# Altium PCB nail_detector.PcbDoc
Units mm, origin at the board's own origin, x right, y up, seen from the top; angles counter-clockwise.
Board outline 180 x 100 mm, 2 copper layers (Top Layer, Bottom Layer); 116 components, 102 nets, 420 pads, 177 vias.
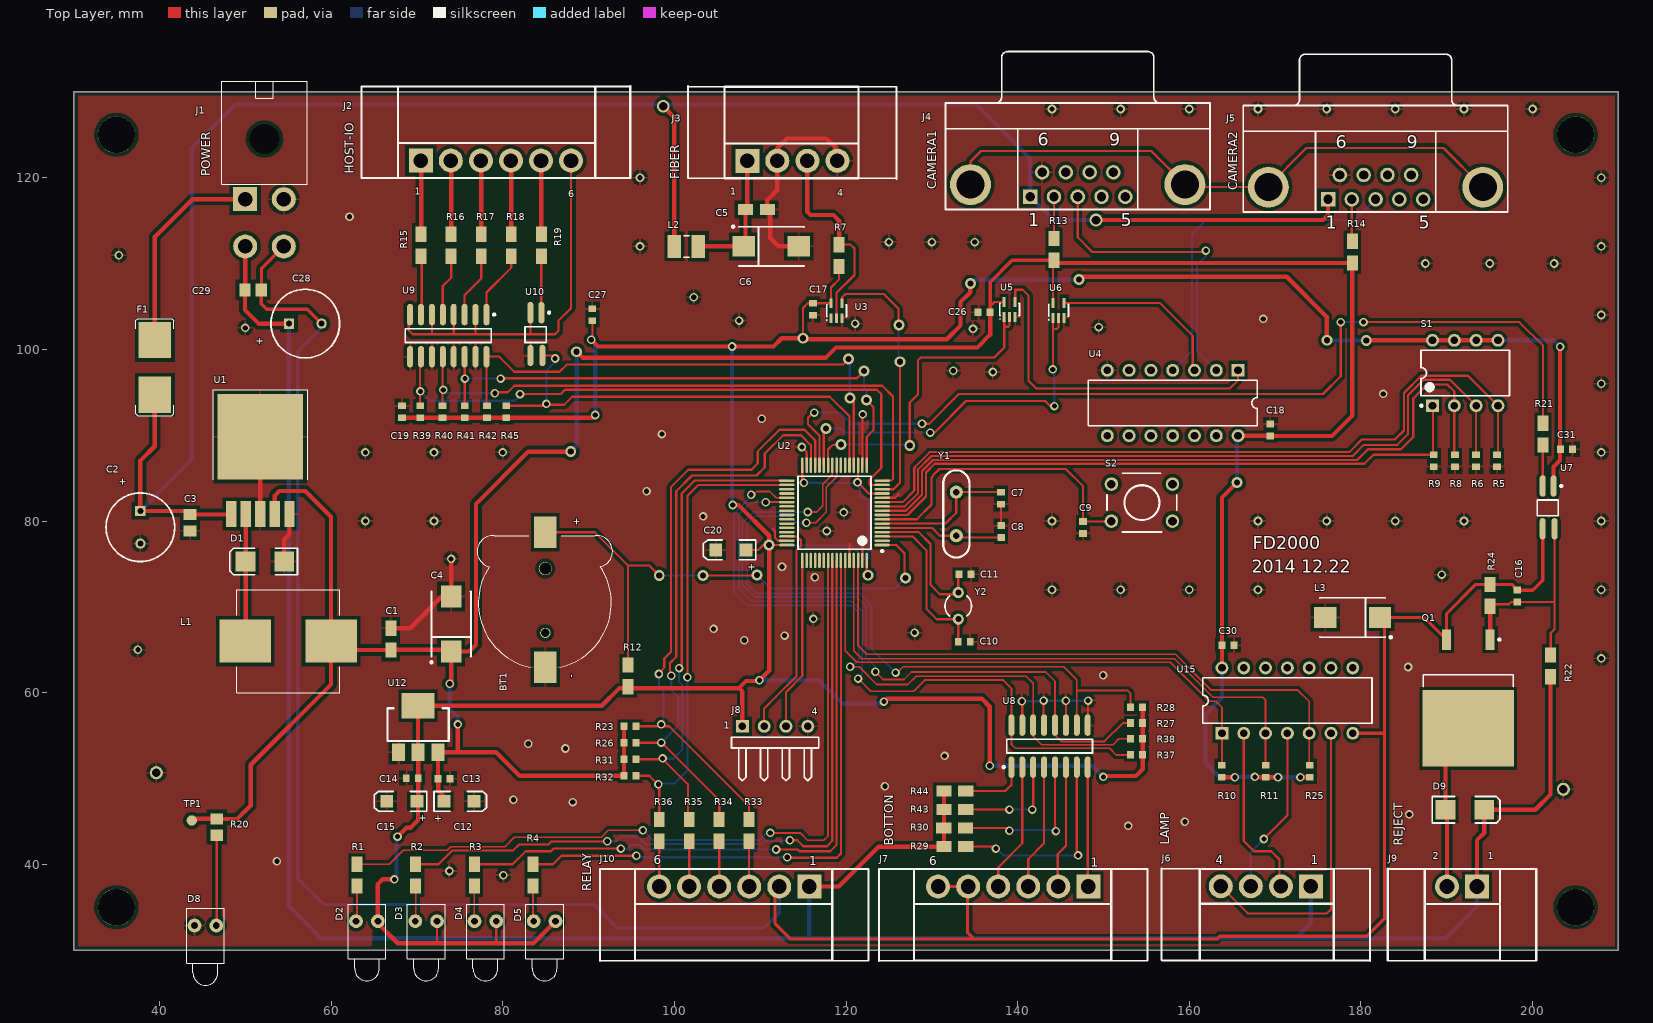
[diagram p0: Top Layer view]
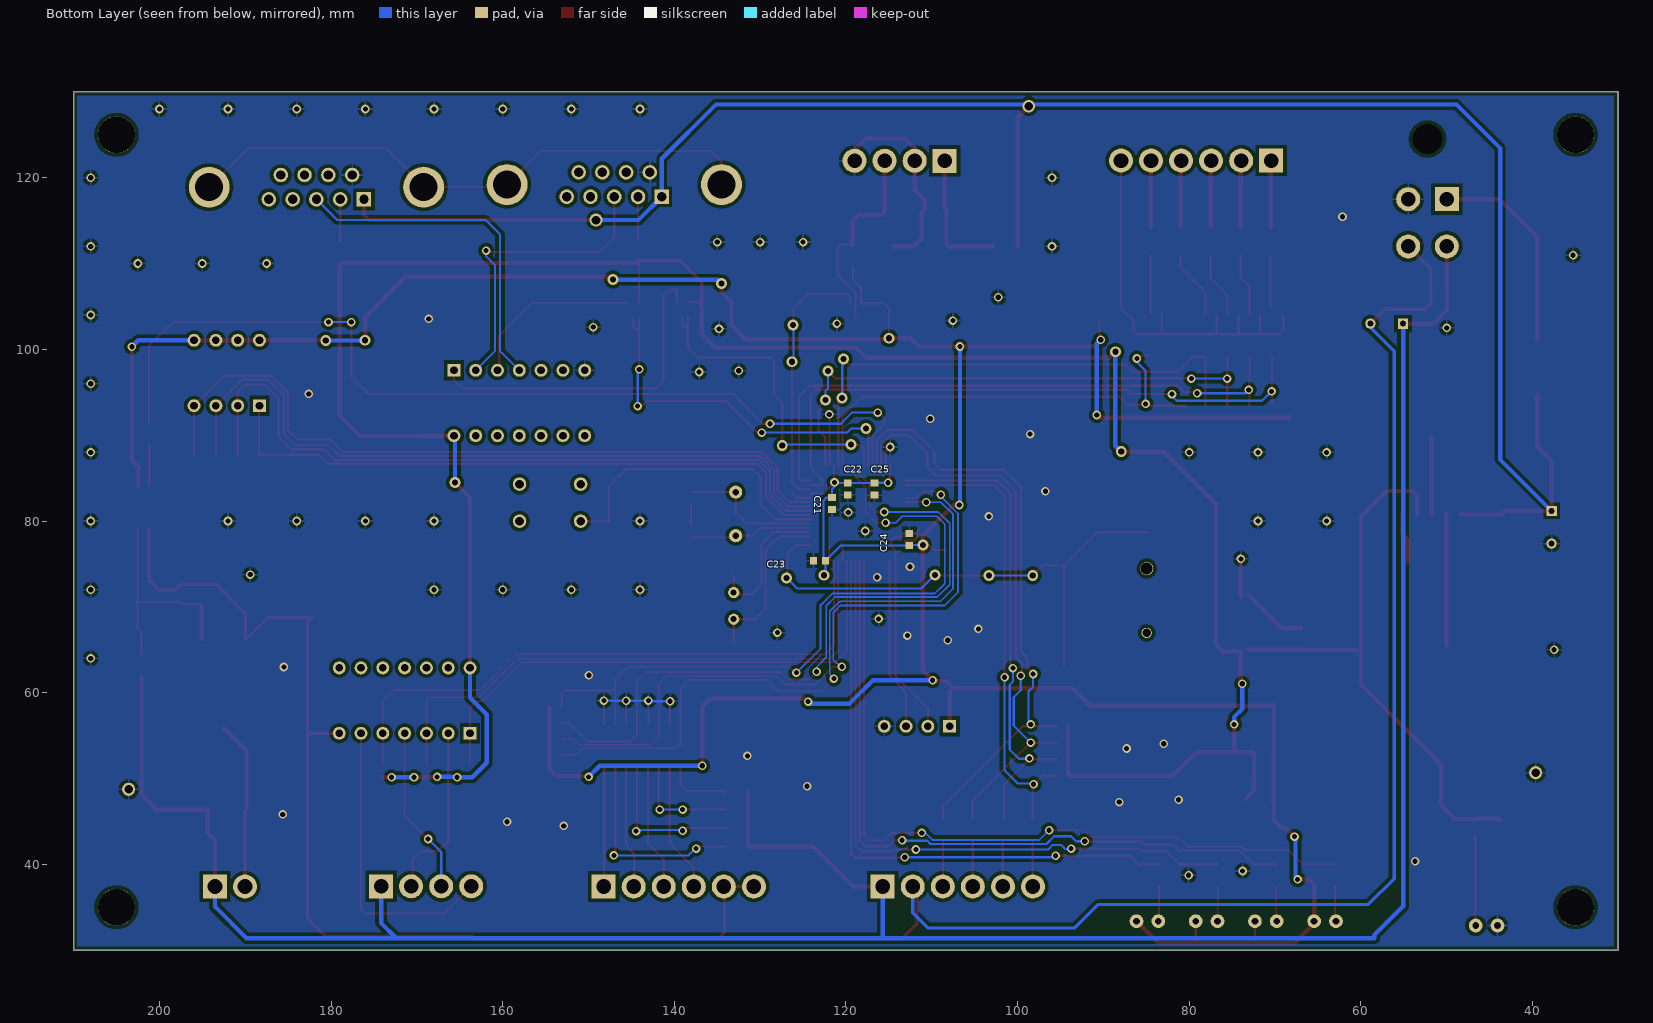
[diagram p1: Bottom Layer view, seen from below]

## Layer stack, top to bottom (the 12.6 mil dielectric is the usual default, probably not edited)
Top Layer: signal copper 0.0356
Dielectric: dielectric 0.32, FR-4, Dk 4.8
Bottom Layer: signal copper 0.0356

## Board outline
30,130 210,130 210,30 30,30

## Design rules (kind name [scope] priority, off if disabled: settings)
Clearance Clearance_u2 [InComponent('U2')] p1 off: gap=0.2
Clearance Clearance_all [All] p2: gap=0.2
Clearance ploy [All] p3 off: gap=0.4
ComponentClearance [All] p1: gap=0.1 collisioncheckmode=3 verticalgap=0.254 showdistances=FALSE
HoleSize [All] p1: absolutevalues=TRUE maxlimit=5 minlimit=0.025 maxpercent=80.000 minpercent=20.000
MinimumSolderMaskSliver [All] p1 off: minsoldermaskwidth=0.254
PolygonConnect [All] p1: connectstyle=Relief reliefconductorwidth=0.254 reliefentries=4 polygonreliefangle="90 Angle"
RoutingVias [All] p1: holewidth=0.6 width=1 viastyle="Through Hole" minholewidth=0.4 minwidth=1 maxholewidth=0.711 maxwidth=1.27
SilkToSilkClearance [All] p1 off: silktosilkclearance=0.1
SilkscreenOverComponentPads [All] p1 off: minsilkscreentomaskgap=0
SolderMaskExpansion [All] p1: expansion=0.102
Width [All] p1: maxlimit=1 minlimit=0.2 preferedwidth=0.254 minimp=50.000000 maximp=50.000000 favimp=50.000000
23 further rules are at their usual default settings.

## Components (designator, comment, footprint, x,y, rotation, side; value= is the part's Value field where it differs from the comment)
BT1 "Battery" CR1220 84.963,70.46 r90 top
C1 "100nF" 0805 66.974,64.974 r90 top
C2 "35V220uF" RB8-12 37.79,79.273 r90 top
C3 "100nF" 6-0805 43.581,79.807 r270 top
C4 "Cap Pol3" 7343 74,68 r90 top
C5 "100nF" 0805 108.3,116.3 r0 top
C6 "Cap Pol3" 7343 111.3,112 r0 top
C7 "Cap" 1608[0603] 138.057,82.655 r90 top
C8 "Cap" 1608[0603] 138.083,78.769 r270 top
C9 "Cap" 1608[0603] 147.625,79.248 r90 top
C10 "Cap" 1608[0603] 133.782,65.938 r180 top
C11 "Cap" 1608[0603] 133.883,73.787 r180 top
C12 "Cap Pol3" 3216-18 74.905,47.346 r0 top
C13 "Cap Semi" 1608[0603] 73.177,49.987 r180 top
C14 "Cap Semi" 1608[0603] 69.469,50.038 r0 top
C15 "Cap Pol3" 3216-18 68.25,47.346 r180 top
C16 "Cap" 1608[0603] 198.222,71.247 r270 top
C17 "Cap Semi" 1608[0603] 116.154,104.673 r90 top
C18 "Cap Semi" 1608[0603] 169.443,90.602 r270 top
C19 "Cap Semi" 1608[0603] 68.275,92.735 r270 top
C20 "Cap Pol3" 3216-18 106.578,76.632 r180 top
C21 "Cap Semi" 1608[0603] 121.641,82.042 r90 bottom
C22 "Cap Semi" 1608[0603] 119.786,83.744 r90 bottom
C23 "Cap Semi" 1608[0603] 123.088,75.387 r180 bottom
C24 "Cap Semi" 1608[0603] 112.624,77.851 r270 bottom
C25 "Cap Semi" 1608[0603] 116.688,83.718 r90 bottom
C26 "Cap Semi" 1608[0603] 136.093,104.318 r0 top
C27 "Cap Semi" 1608[0603] 90.449,104.038 r270 top
C28 "35V220uF" RB8-12 57,103 r180 top
C29 "100nF" 6-0805 50.927,106.934 r0 top
C30 "Cap Semi" 1608[0603] 164.516,65.532 r180 top
C31 "Cap Semi" 1608[0603] 203.962,88.367 r180 top
D1 "SS24" SMB 52.293,75.286 r180 top
D2 "" LED-1 64.186,33.376 r270 top
D3 "" LED-1 71.086,33.376 r270 top
D4 "" LED-1 77.986,33.376 r270 top
D5 "" LED-1 84.887,33.376 r270 top
D8 "" LED-1 45.364,32.868 r270 top
D9 "SS24" SMB 192.1,46.355 r0 top
F1 "LITTLEFUSE154-002" LTFS154 39.472,101.092 r270 top
J1 "Header 4H" 5569-4A 50,117.5 r180 top
J2 "" 3500-6 70.46,121.996 r0 top
J3 "Header 4" 3500-4 108.5,121.971 r0 top
J4 "D Connector 9" DSUB1.385-2H9 147,128.7 r0 top
J5 "D Connector 9" DSUB1.385-2H9 181.7,128.4 r0 top
J6 "Header 4" 3500-4 174.168,37.44 r180 top
J7 "" 3500-6 148.234,37.414 r180 top
J8 "Header 4" HDR1X4H 107.925,56.083 r0 top
J9 "Header 2" 3500-2 193.523,37.414 r180 top
J10 "" 3500-6 115.722,37.414 r180 top
L1 "33uH/2.1A" CDRH1205 55,66 r90 top
L2 "Inductor" 3225[1210] 101.397,111.989 r180 top
L3 "33uH/2.1A" 7343 179.019,68.758 r180 top
Q1 "IRF530NS" D2PAK_N 192.507,59.385 r270 top
R1 "Res Semi" 0805 63.017,40.005 r270 top
R2 "Res Semi" 0805 69.858,40.005 r270 top
R3 "Res Semi" 0805 76.7,40.005 r270 top
R4 "Res Semi" 0805 83.541,40.005 r270 top
R5 "Res Semi" 1608[0603] 195.859,87.02 r90 top
R6 "Res Semi" 1608[0603] 193.404,87.02 r90 top
R7 "Res2" 0805 119.2,112.2 r270 top
R8 "Res Semi" 1608[0603] 190.949,87.02 r90 top
R9 "Res Semi" 1608[0603] 188.493,87.02 r90 top
R10 "Res Semi" 1608[0603] 163.779,50.851 r270 top
R11 "Res Semi" 1608[0603] 168.91,50.851 r270 top
R12 "Res2" 0805 94.615,60.681 r90 top
R13 "Res2" 0805 144.247,112.928 r270 top
R14 "Res2" 0805 178.994,112.598 r270 top
R15 "Res Semi" 0805 70.5,113.4 r270 top
R16 "Res Semi" 0805 74,113.4 r270 top
R17 "Res Semi" 0805 77.5,113.4 r270 top
R18 "Res Semi" 0805 81,113.4 r270 top
R19 "Res Semi" 0805 84.5,113.4 r270 top
R20 "Res Semi" 2012[0805] 46.685,44.348 r90 top
R21 "Res Semi" 0805 201.219,91.389 r270 top
R22 "Res Semi" 0805 202.082,61.849 r90 top
R23 "Res Semi" 1608[0603] 94.844,56.083 r180 top
R24 "Res Semi" 0805 195.047,70.068 r90 top
R25 "Res Semi" 1608[0603] 174.041,50.851 r270 top
R26 "Res Semi" 1608[0603] 94.844,54.161 r180 top
R27 "Res Semi" 1608[0603] 153.859,56.456 r0 top
R28 "Res Semi" 1608[0603] 153.859,58.293 r0 top
R29 "Res Semi" 0805 133.96,42.062 r180 top
R30 "Res Semi" 0805 133.934,44.221 r180 top
R31 "Res Semi" 1608[0603] 94.844,52.239 r180 top
R32 "Res Semi" 1608[0603] 94.844,50.317 r180 top
R33 "Res Semi" 0805 108.712,42.697 r90 top
R34 "Res Semi" 0805 105.224,42.697 r90 top
R35 "Res Semi" 0805 101.735,42.697 r90 top
R36 "Res Semi" 0805 98.247,42.697 r90 top
R37 "Res Semi" 1608[0603] 153.859,52.781 r0 top
R38 "Res Semi" 1608[0603] 153.859,54.618 r0 top
R39 "Res Semi" 1608[0603] 70.383,92.735 r270 top
R40 "Res Semi" 1608[0603] 72.983,92.735 r270 top
R41 "Res Semi" 1608[0603] 75.582,92.735 r270 top
R42 "Res Semi" 1608[0603] 78.181,92.735 r270 top
R43 "Res Semi" 0805 133.96,46.38 r180 top
R44 "Res Semi" 0805 133.96,48.539 r180 top
R45 "Res Semi" 1608[0603] 80.416,92.735 r270 top
S1 "SW-DIP4" DIP-8 192.147,97.245 r90 top
S2 "SW-PB" BUTTON6*6*6 150.927,84.303 r0 top
TP1 "TP" TP1 43.764,45.11 r90 top
U1 "LM2596S-5.0" TO-263 51.76,89.814 r0 top
U2 "STM32F103R6T6" LQFP64_N 118.658,80.953 r180 top
U3 "NC7SZ14P5X" SC70-5 118.9,104.5 r0 top
U4 "SN7407N" N014 158.064,93.751 r180 top
U5 "NC7S08" SC70-5 139.064,104.645 r0 top
U6 "NC7S08" SC70-5 144.764,104.545 r0 top
U7 "ps2801-1" SO-4_M 202.438,83.922 r270 top
U8 "ps2801-4" SO-16_M 143.713,53.772 r90 top
U9 "ps2801-4" SO-16_M 73.66,101.6 r270 top
U10 "ps2801-1" SO-4_M 84.506,104.115 r270 top
U12 "AS1117M3-33" SOT-223/P2.3 67.836,53.01 r0 top
U15 "SN7407N" N014 171.425,59.08 r0 top
Y1 "XTAL" XTAL-A 132.85,78.286 r90 top
Y2 "XTAL" R38 133.079,70.108 r0 top

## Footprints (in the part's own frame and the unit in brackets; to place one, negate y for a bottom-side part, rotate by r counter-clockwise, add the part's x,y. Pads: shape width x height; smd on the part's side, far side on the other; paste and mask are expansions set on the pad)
6-0805 [mm] "Chip Resistor; Body 2.0 x 1.3 mm (LxW typ)"
  rect 1.3x1.5 smd: 1(-0.95,0) 2(0.95,0)
0805 [mil]
  rect 70x50 smd: 1(0,0) 2(100,0)
1608[0603] [mm] "Chip Capacitor, Body 1.6x0.8mm, IPC High Density"
  rect 0.8x0.9 smd: 1(-0.7,0) 2(0.7,0)
  body extent -0.87,-0.48 0.87,0.48, height 1.3
2012[0805] [mm] "Chip Resistor; Body 2.0 x 1.3 mm (LxW typ)"
  rect 1.3x1.5 smd: 1(-0.95,0) 2(0.95,0)
3216-18 [mm]
  rect 1.5x1.5 smd: 1(-1.75,0) 2(1.75,0)
  silkscreen extent -2.9,-1.15 3.2,1.15, body extent -1.63,-0.8 1.57,0.8, height 1.6
3225[1210] [mm] "Chip Resistor; Body 3.2 x 2.5 mm (LxW typ)"
  rect 1.6x2.7 smd: 1(-1.4,0) 2(1.4,0)
  silkscreen extent -0.3,-1.25 0.3,1.25
3500-2 [mil]
  rect 110x110 hole 66.93: 1(0,0)
  round 110 hole 66.93: 2(137.8,0)
  silkscreen extent -272,-82 409,340, body extent -272,-80 409,341, height 315
3500-4 [mil]
  rect 110x110 hole 66.93: 1(0,0)
  round 110 hole 66.93: 2(137.79,0) 3(275.59,0) 4(413.39,0)
  silkscreen extent -272,-82 685,342, body extent -272,-80 685,331, height 315
3500-6 [mil]
  rect 110x110 hole 66.93: 1(0,0)
  round 110 hole 66.93: 2(137.8,0) 3(275.59,0) 4(413.39,0) 5(551.18,0) 6(688.98,0)
  silkscreen extent -272,-80 961,341, body extent -272,-80 961,330, height 315
5569-4A [mil] "MOLEX 5569-4A"
  round 60 hole 137.8 unplated: 0(-88.58,-275.59)
  rect 110x110 hole 66.93: 1(0,0)
  round 110 hole 66.93: 2(-177.17,0) 3(0,216.54) 4(-177.17,216.54)
  silkscreen extent -285,-541 108,-69
7343 [mm] "Capacitor, SM Tantalum; Body 7.3 x 4.3 mm (LxW typ)"
  rect 2.6x2.4 smd: 1(-3.2,0) 2(3.2,0)
  silkscreen extent -4.57,-2.3 3.8,2.42
BUTTON6*6*6 [mil]
  round 62 hole 39.37: 1(0,0) 2(0,-170) 3(280,-170) 4(280,0)
  silkscreen extent -20,-220 300,50, body extent -13,-208 299,36, height 276
CDRH1205 [mm]
  rect 5x6 smd: 1(0,5) 2(0,-5)
  silkscreen extent -6,-6 6,6, body extent -6.02,-5.94 5.93,6.03, height 6
CR1220 [mm] "battery cr1220"
  round 1.2 hole 1: 0(-3.5,0)
  round 1.524 hole 1.4: 0(4,0)
  rect 3.7x2.6 smd: 1(8.23,0) 2(-7.5,0)
  silkscreen extent -7.51,-7.83 7.83,7.93
D2PAK_N [mm] "D2-PAK, 4-Leads, Body 8.8x10.4mm, Pitch 2.54mm, Lead Span 15.1mm, IPC Medium Density"
  rect 2.4x1.05 smd: 1(-6.8,2.54) 3(-6.8,-2.54)
  rect 8.9x10.65 smd: 2(3.55,0)
  silkscreen extent -6.92,-5.25 -1.3,5.25, body extent -2.7,-5.28 6.3,5.28, height 4.69
DIP-8 [mm] "DIP; 8 Leads; Row Spacing 7.62 mm; Pitch 2.54 mm"
  rect 1.5x1.5 hole 0.9: 1(-3.81,3.81)
  round 1.5 hole 0.9: 2(-3.81,1.27) 3(-3.81,-1.27) 4(-3.81,-3.81) 5(3.81,-3.81) 6(3.81,-1.27) 7(3.81,1.27) 8(3.81,3.81)
  silkscreen extent -3.93,-5.15 2.65,5.23, body extent -3.6,-5.15 3.6,5.15, height 5.08
DSUB1.385-2H9 [mm] "Connector; D Subminiature; 9 Position; Right Angle; Pitch 1.385 mm"
  rect 1.69x1.69 hole 1.09: 1(-5.54,-10.92)
  round 1.69 hole 1.09: 2(-2.77,-10.92) 3(0,-10.92) 4(2.77,-10.92) 5(5.54,-10.92) 6(-4.155,-8.08) 7(-1.385,-8.08) 8(1.385,-8.08) 9(4.155,-8.08)
  round 4.76 hole 3.26: 10(-12.495,-9.5) 11(12.495,-9.5)
  silkscreen extent -15.4,-12.4 15.4,6
HDR1X4H [mm] "Connector; Header; 4 Position; Right Angle"
  rect 1.5x1.5 hole 0.9: 1(0,0)
  round 1.5 hole 0.9: 2(2.54,0) 3(5.08,0) 4(7.62,0)
  silkscreen extent -1.27,-6.35 8.89,-1.27
LED-1 [mm] "LED; 2 Leads"
  round 1.6 hole 0.8: 1(0,1.27) 2(0,-1.27)
  silkscreen extent -2,-2.2 6.95,2.2
LQFP64_N [mm] "Thin QFP, 64-Leads, Body 10x10mm, Pitch 0.5mm, IPC Medium Density"
  oval 1.8x0.3 smd: 1(-5.55,3.75) 2(-5.55,3.25) 3(-5.55,2.75) 4(-5.55,2.25) 5(-5.55,1.75) 6(-5.55,1.25) 7(-5.55,0.75) 8(-5.55,0.25) 9(-5.55,-0.25) 10(-5.55,-0.75) 11(-5.55,-1.25) 12(-5.55,-1.75) 13(-5.55,-2.25) 14(-5.55,-2.75) 15(-5.55,-3.25) 16(-5.55,-3.75) 33(5.55,-3.75) 34(5.55,-3.25) 35(5.55,-2.75) 36(5.55,-2.25) 37(5.55,-1.75) 38(5.55,-1.25) 39(5.55,-0.75) 40(5.55,-0.25) 41(5.55,0.25) 42(5.55,0.75) 43(5.55,1.25) 44(5.55,1.75) 45(5.55,2.25) 46(5.55,2.75) 47(5.55,3.25) 48(5.55,3.75)
  oval 0.3x1.8 smd: 17(-3.75,-5.55) 18(-3.25,-5.55) 19(-2.75,-5.55) 20(-2.25,-5.55) 21(-1.75,-5.55) 22(-1.25,-5.55) 23(-0.75,-5.55) 24(-0.25,-5.55) 25(0.25,-5.55) 26(0.75,-5.55) 27(1.25,-5.55) 28(1.75,-5.55) 29(2.25,-5.55) 30(2.75,-5.55) 31(3.25,-5.55) 32(3.75,-5.55) 49(3.75,5.55) 50(3.25,5.55) 51(2.75,5.55) 52(2.25,5.55) 53(1.75,5.55) 54(1.25,5.55) 55(0.75,5.55) 56(0.25,5.55) 57(-0.25,5.55) 58(-0.75,5.55) 59(-1.25,5.55) 60(-1.75,5.55) 61(-2.25,5.55) 62(-2.75,5.55) 63(-3.25,5.55) 64(-3.75,5.55)
  silkscreen extent -5.68,-4.25 4.25,4.57, body extent -5,-5 5,5, height 1.6
LTFS154 [mm] "little fuse 154"
  rect 4.24x3.81 smd: 1(0,0) 2(6.37,0)
  silkscreen extent -2.5,-2.2 8.8,2.2
N014 [mm] "DIP; 14 Leads; Row Spacing 7.62 mm; Pitch 2.54 mm"
  rect 1.5x1.5 hole 0.9: 1(-7.62,-3.81)
  round 1.5 hole 0.9: 2(-5.08,-3.81) 3(-2.54,-3.81) 4(0,-3.81) 5(2.54,-3.81) 6(5.08,-3.81) 7(7.62,-3.81) 8(7.62,3.81) 9(5.08,3.81) 10(2.54,3.81) 11(0,3.81) 12(-2.54,3.81) 13(-5.08,3.81) 14(-7.62,3.81)
  silkscreen extent -9.85,-2.65 9.85,2.65
R38 [mm] "Crystal, Thru-Hole; 2 Leads; Body 3.1 x 8.2 mm (Dia.xH)"
  round 1.3 hole 0.7: 1(0,1.55) 2(0,-1.55)
  silkscreen extent -1.55,-1.19 1.55,1.17
RB8-12 [mm] "Polarized Capacitor (Radial); 2 Leads,D=8,H=12"
  rect 1.2x1.2 hole 0.7: 1(1.905,0)
  round 1.2 hole 0.7: 2(-1.905,0)
  silkscreen extent -4,-4 4,4, body extent -3.9,-3.94 4.06,4.05, height 8
SC70-5 [mm] "SOT-353/SC-88A; 5 Leads; Body 2.2 x 2.4 mm, inc. leads (LxW max)"
  rect 0.35x1.15 smd: 1(-0.65,-0.875) 2(0,-0.875) 3(0.65,-0.875) 4(0.65,0.875) 5(-0.65,0.875)
  silkscreen extent -1.17,-1.15 1.15,0.7, body extent -1,-1.1 1,1.1, height 0.49
SMB [mm] "DO-214-AA/SMB; 2 C-Bend Leads; Body 5.3 x 3.6 mm, inc. leads (LxW)"
  rect 2.3x2.3 smd: 1(-2.25,0) 2(2.25,0)
  silkscreen extent -3.8,-1.55 4.1,1.55
SO-4_M [mm] "SOIC, 16-Leads, Body 9.9x3.9mm, Pitch 1.27mm, IPC Low Density"
  oval 2.5x0.7 smd: 1(-0.164,0) 2(-0.164,-1.27) 3(4.826,-1.27) 4(4.826,0.127)
  silkscreen extent -0.29,-1.9 3.3,1.03
SO-16_M [mm] "SOIC, 16-Leads, Body 9.9x3.9mm, Pitch 1.27mm, IPC Low Density"
  oval 2.5x0.7 smd: 1(-2.45,4.445) 2(-2.45,3.175) 3(-2.45,1.905) 4(-2.45,0.635) 5(-2.45,-0.635) 6(-2.45,-1.905) 7(-2.45,-3.175) 8(-2.45,-4.445) 9(2.45,-4.445) 10(2.45,-3.175) 11(2.45,-1.905) 12(2.45,-0.635) 13(2.45,0.635) 14(2.45,1.905) 15(2.45,3.175) 16(2.45,4.445)
  silkscreen extent -2.57,-5 0.8,5.47, body extent -2,-5 2,5, height 1.75
SOT-223/P2.3 [mil]
  rect 59x79 smd: 1(0.61,1.72) 2(91.16,1.72) 3(181.71,1.72)
  rect 150x119 smd: 4(90.49,215.26)
  silkscreen extent -49,54 231,204
TO-263 [mm]
  rect 1.2x3 smd: 1(-3.4,-9) 2(-1.7,-9) 3(0,-9) 4(1.7,-9) 5(3.4,-9)
  rect 10x10 smd: 6(0,0)
  silkscreen extent -5.5,-5.02 5.5,5.5, body extent -5.49,-5.84 5.31,5.21, height 4
TP1 [mm]
  round 1.2 smd: 1(0,-0.02)
XTAL-A [mil]
  round 60 hole 30: 1(0,0) 2(200,0)
  silkscreen extent -100,-60 300,60, body extent -115,-95 325,89, height 143

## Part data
BT1: "Multicell Battery"
C1 C3 C5 C29: library part CAP
C2 C28: library part "CAPACITOR POL", "Polarized Capacitor (Radial); 35V;220uF;D=8,H=12"
C4 C6: "Polarized Capacitor (Surface Mount);220uF;16V;7343"
C7 C8 C9 C10 C11 C16: "Capacitor"
C12 C15 C20: "Polarized Capacitor (Surface Mount)"
C13 C14 C17 C18 C19 C21 C22 C23 C24 C25 C26 C27 C30 C31: "Capacitor (Semiconductor SIM Model)"
D1 D9: library part "D Schottky", "Schottky Diode; SS24; 40V;2A;SMB"
D2 D3 D4 D5 D8: library part LED1, "Typical RED GaAs LED"
F1: library part "Fuse 1", "Fuse"
J1: "Header, 4-Pin, Right Angle"
J2 J7 J10: library part "Header 6", "Header, 6-Pin"
J3 J6 J8: "Header, 4-Pin"
J4 J5: "Receptacle Assembly, 9 Position, Right Angle"
J9: "Header, 2-Pin"
L1 L3: library part L, "CDRH1205-330M；大功率屏蔽贴片"
Q1: "HEXFET Power MOSFET"
R1 R2 R3 R4 R5 R6 R8 R9 R10 R11 R15 R16 R17 R18 R19 R20 R21 R22 R23 R24 R25 R26 R27 R28 R29 R30 R31 R32 R33 R34 R35 R36 R37 R38 R39 R40 R41 R42 R43 R44 R45: "Semiconductor Resistor"
R7 R12 R13 R14: "Resistor"
S1: "DIP Switch"
S2: "Switch"
TP1: "Test Point"
U1: "Buck regulator; 5.0V;3A; TO-263;TI"
U2: "STM32 ARM-based 32-bit MCU with 32 Kbytes Flash, 64-pin LQFP, Industrial Temperature"
U3: library part NC7SZ14
U4 U15: "Hex Buffer / Driver with Open-Collector High-Voltage Outputs"
U12: library part AS1117-50
Y1 Y2: "Crystal Oscillator"

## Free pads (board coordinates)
  round 4.3 hole 4.3 unplated: 0(35,125) 1(35,35) 2(205,35) 3(205,125)
  round 1.524 hole 1: 0(39.649,50.673) 1(203.581,48.743)

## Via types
v1: diameter 1, hole 0.6, Top Layer to Bottom Layer, 152 vias
v2: diameter 1.27, hole 0.711, Top Layer to Bottom Layer, 23 vias
v3: diameter 1.5, hole 1, Top Layer to Bottom Layer, 2 vias

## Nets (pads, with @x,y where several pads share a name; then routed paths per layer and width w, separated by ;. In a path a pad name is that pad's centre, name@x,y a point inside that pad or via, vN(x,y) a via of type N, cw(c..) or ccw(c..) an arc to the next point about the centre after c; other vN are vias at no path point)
24GND: C16.1 C28.2 C29.2 J1.4 J7.5 J7.6 J10.2 L3.1 Q1.3 R24.2 U7.3 U15.7 | length 301.3
  Top Layer w0.381: J1.4 51.892,109.392 51.892,106.949 C29.2 51.877,105.324 52.527,104.673 57.232,104.673 C28.2 ; J10.2 111.735,36.926 111.735,33.096 113.538,31.293 134.925,31.293 ; J7.6 J7.5 134.163,37.343 134.163,32.055 134.925,31.293 ; U15.7 182.575,55.27 182.753,55.093 ; U7.3 201.168,73.101 200.014,71.947 C16.1 197.561,72.608 R24.2 193.385,72.608 189.967,69.19 Q1.3 187.394,68.758 L3.1 182.753,68.224 182.753,55.093 ; 134.925,31.293 163.22,31.293 163.551,31.623 180.67,31.623 182.753,33.706 182.753,55.093
  Bottom Layer w0.381: C28.2 58.905,102.568 56.134,99.797 56.134,38.329 59.131,35.331 90.602,35.331 93.345,32.588 110.465,32.588 112.222,34.346 J10.2
+3.3V: C14.2 C15.1 C17.2 C19.2 C20.1 C21.2 C22.2 C23.2 C24.2 C25.2 C27.2 C31.2 D2.1 D3.1 D4.1 D5.1 J8.1 R7.2 R12.1 R27.2 R28.2 R37.2 R38.2 R39.2 R40.2 R41.2 R42.2 R45.2 S1.5 S1.6 S1.7 S1.8 U2.13 U2.19 U2.32 U2.48 U2.64 U3.5 U7.1 U12.2 U12.4 | length 435.2
  Top Layer w0.254: 72.356,31.115 D3.1 ; 79.256,30.912 D4.1 ; v1@90.449,100.99 C27.2 ; C20.1 109.779,76.632 110.363,77.216 v2(111.049,77.216) 111.061,77.203 U2.48 ; U2.32 114.908,84.634 v1(115.087,84.455) ; v2@114.986,101.194 v2(114.986,101.295) 114.986,104.826 115.533,105.373 C17.2 U3.5@118.248,105.373 ; U3.5 118.25,107.201 119.2,108.151 R7.2 ; U2.19 121.408,84.578 v1(121.336,84.506) 122.638,83.203 U2.13 ; U2.64 122.408,73.832 v2(122.555,73.685)
  Top Layer w0.5: v1(67.386,38.252) 66.015,38.252 65.456,37.694 D2.1 65.456,33.122 67.767,30.81 83.591,30.81 D5.1 ; v1(67.742,43.231) 68.783,44.272 69.263,44.272 70.127,45.136 70.127,46.99 70.169,47.032 C14.2 70.169,53.037 U12.2 70.135,53.071 U12.4 91.549,58.478 93.599,60.528 107.518,60.528 ; C19.2 R39.2 R40.2 R41.2 R42.2 R45.2@80.34,92.035 ; R45.2 90.461,92.035 v1(90.78,92.354) ; v1(90.322,101.117) 90.449,100.99 91.11,100.33 v1(106.731,100.33) 111.557,100.33 112.522,101.295 v2(114.986,101.295) 115.106,101.175 131.732,101.175 133.35,102.794 133.35,105.512 134.493,106.655 v2(134.493,107.671) ; v1(106.807,81.864) 107.467,81.864 111.049,78.283 v2(111.049,77.216) 111.049,62.586 v1(109.906,61.443) 110.211,61.443 110.134,61.366 108.356,61.366 107.518,60.528 ; J8.1 107.925,60.122 107.518,60.528 ; v1(124.409,58.953) 124.765,59.309 135.814,59.309 136.754,58.369 v1(136.754,51.486) ; v2(147.142,108.153) 147.447,108.458 171.348,108.458 176.022,103.784 v2(176.022,101.067) ; v1(149.987,50.19) 150.089,50.292 153.772,50.292 154.559,51.079 R37.2 R38.2 R27.2 R28.2 ; v2(180.619,101.041) 180.633,101.055 S1.8 S1.7 S1.6 S1.5 ; U7.1 202.438,86.309 203.2,87.071 v1(203.2,100.305)
  Bottom Layer w0.254: v2(111.049,77.216) 112.559,77.216 C24.2 120.625,77.151 C23.2 ; v1(115.087,84.455) C25.2@116.651,84.455 ; C25.2 C22.2@119.761,84.418 ; C22.2 v1@121.274,84.444 ; v1(121.336,84.506) 121.336,84.023 121.641,83.718 C21.2 122.261,82.742 122.606,82.398 122.606,75.605 C23.2 ; v2(122.555,73.685) 122.388,73.852 C23.2
  Bottom Layer w0.5: v1(67.386,38.252) 67.64,38.506 67.64,43.129 v1(67.742,43.231) ; v1(90.322,101.117) 90.78,100.66 v1(90.78,92.354) ; v1@106.604,99.949 106.604,99.924 106.716,99.811 106.716,81.955 v1(106.807,81.864) ; v1(109.906,61.443) 116.865,61.443 119.583,58.725 124.181,58.725 v1(124.409,58.953) ; v2(134.493,107.671) 134.925,108.102 147.091,108.102 v2(147.142,108.153) ; v1(136.754,51.486) 148.692,51.486 v1(149.987,50.19) ; v2(176.022,101.067) 176.047,101.041 v2(180.619,101.041) ; S1.5 202.45,101.055 v1(203.2,100.305)
+5V: C1.1 C4.1 C12.1 C13.2 C18.2 C26.2 C30.2 L1.2 R10.2 R11.2 R13.2 R14.2 R20.2 R23.2 R25.2 R26.2 R31.2 R32.2 TP1.1 U1.4 U4.14 U5.5 U6.5 U12.3 U15.14 | length 356.2
  Top Layer w0.254: 136.793,102.325 136.855,102.387 136.855,105.063 137.312,105.52 U5.5 ; U6.5 144.114,110.255 R13.2
  Top Layer w0.3: v2@88.062,99.72 v2(88.621,99.72)
  Top Layer w0.4: C26.2 136.793,107.837 139.344,110.388 R13.2
  Top Layer w0.5: TP1.1@43.764,45.11 43.952,45.298 R20.2 ; R20.2@46.05,45.273 49.058,45.273 50.648,46.863 50.648,51.613 60,60.965 L1.2 59.985,65.985 59.985,80.496 56.992,83.49 53.969,83.49 53.46,82.98 U1.4 ; L1.2@60.468,64.974 C1.1 67,65 C4.1@73.121,65 ; C12.1@73.453,47.644 72.477,48.619 C13.2 72.452,50.013 U12.3 74.6,53.054 ; v1(73.838,61.036) 74.016,60.858 74.092,60.858 74,60.95 C4.1 76.179,64.8 76.179,64.876 76.886,65.583 76.886,81.991 82.982,88.087 v2(87.935,88.087) ; v1(74.778,56.312) 74.778,53.232 74.6,53.054 ; v2(88.621,99.72) 89.306,99.035 117.653,99.035 118.847,100.228 135.306,100.228 136.793,101.716 136.793,102.325 C26.2 ; R23.2 R26.2 R31.2 R32.2 81.966,50.317 79.229,53.054 74.6,53.054 ; R13.2@144.311,110.058 R14.2 178.994,92.278 176.617,89.902 C18.2 169.404,89.941 U4.14 ; R10.2 163.79,50.14 v1(165.303,50.14) ; U15.14 163.805,65.521 C30.2 163.816,82.739 v2(165.557,84.48) ; v1(167.64,50.19) 167.68,50.151 R11.2 168.921,50.14 v1(170.332,50.14) ; v1(172.949,50.14) 172.96,50.151 R25.2
  Bottom Layer w0.5: v1(73.838,61.036) 73.838,58.09 74.778,57.15 v1(74.778,56.312) ; v2(87.935,88.087) 88.621,88.773 v2(88.621,99.72) ; 162.865,58.42 162.814,58.42 ; U15.14 163.805,59.411 162.814,58.42 ; v2(165.557,84.48) 165.557,89.814 U4.14 ; v1(167.64,50.19) 165.532,50.19 165.43,50.089 165.354,50.089 v1(165.303,50.14) 163.551,50.14 161.849,51.841 161.849,57.455 162.814,58.42 ; v1(170.332,50.14) v1(172.949,50.14)
+12V: C2.1 C3.1 F1.2 J4.1 J5.1 L2.2 U1.1 | length 231.3
  Top Layer w0.5: F1.2 39.472,88.722 37.79,87.04 C2.1 43.159,81.178 C3.1 48.302,80.757 U1.1 ; v3(98.704,128.321) 99.997,127.028 L2.2 ; v3(149.123,115.062) 175.565,115.062 176.16,115.657 J5.1
  Bottom Layer w0.5: C2.1 43.79,87.178 43.79,123.444 48.87,128.524 135.153,128.524 141.46,122.217 J4.1 144.178,115.062 v3(149.123,115.062)
+12VIN: F1.1 J1.1 | length 25.4
  Top Layer w0.5: F1.1 39.472,113.106 43.865,117.5 J1.1
  Bottom Layer w0.5: J1.1@48.92,117.5 J1.1
+24V: C28.1 C29.1 D9.2 J1.3 J6.1 J9.1 J10.1 R22.1 R29.2 R30.2 R43.2 R44.2 | length 293.5
  Top Layer w0.508: J1.3 50,106.957 C29.1 49.977,104.582 51.559,103 C28.1 ; J10.1 119.151,37.414 123.8,42.062 R29.2 R43.2 R44.2 ; J9.1 193.523,42.824 194.35,43.652 D9.2 200.304,46.355 202.082,48.133 R22.1
  Bottom Layer w0.508: C28.1 55.095,35.126 58.471,31.75 58.471,31.394 115.621,31.394 ; J10.1 115.722,31.496 115.621,31.394 ; J6.1 174.168,33.172 172.39,31.394 ; J9.1 193.523,35.077 189.84,31.394 172.39,31.394 ; 115.621,31.394 172.39,31.394
EARTH: J4.10 J4.11 J5.10 J5.11 | length 68.4
  Top Layer w0.254: J4.10 134.505,121.881 135.738,123.114 155.581,123.114 J4.11 159.795,118.9 169.065,118.9 173.634,123.469 189.626,123.469 J5.11
GND: BT1.2 C1.2 C2.2 C3.2 C4.2 C5.2 C6.2 C7.1 C8.1 C9.1 C10.1 C11.1 C12.2 C13.1 C14.1 C15.2 C17.1 C18.1 C19.1 C20.2 C21.1 C22.1 C23.1 C24.1 C25.1 C26.1 C27.1 C30.1 C31.1 D1.1 D8.2 J1.2 J3.2 J3.4 J4.6 J5.6 J8.4 L3.2 pad.0@39.649,50.673 pad.1@203.581,48.743 R5.1 R6.1 R8.1 R9.1 U1.3 U1.5 U1.6 U2.12 U2.18 U2.31 U2.47 U2.60 U2.63 U3.3 U4.7 U5.3 U6.3 U8.9 U8.11 U8.13 U8.15 U9.9 U9.11 U9.13 U9.15 U10.3 U12.1 | length 90.6
  Top Layer w0.254: 111.506,79.045 111.735,78.816 111.735,78.054 112.085,77.703 U2.47 U2.47@113.085,77.726 ; v1(114.859,88.621) 115.408,88.071 U2.31 115.431,86.526 115.431,87.73 ; U2.60 120.408,77.381 ; U2.63 121.908,76.999 ; U2.18 121.908,87.662 121.908,92.394 v1(121.945,92.431) ; U2.12 125.731,82.703 126.136,83.109 ; C8.1@138.057,79.494 C7.1 ; v1(140.487,59.004) 140.538,58.953 U8.15 ; v1(143.027,59.08) 143.027,56.273 U8.13 ; U8.11 v1(145.618,59.055) ; U8.9 148.209,56.273 v1(148.209,59.08)
  Top Layer w0.5: U1.3 U1.6 ; D1.1 54.543,77.84 55.16,78.457 U1.5 ; C1.2 69.235,67.514 C4.2@73.121,71.4 ; v1(73.99,75.59) 74,75.581 C4.2 ; C6.2 112.155,112 111.176,112.979 111.176,115.964 C5.2 110.84,117.419 112,118.579 J3.2 112,123.43 113.132,124.562 117.704,124.562 119,123.265 J3.4
  Bottom Layer w0.254: v1(140.487,59.004) 142.951,59.004 v1(143.027,59.08) 143.053,59.055 v1(145.618,59.055) 147.777,59.055 v1@148.184,59.461
  other v1: 80.089,38.728 73.789,39.228 53.696,40.361 152.883,44.475 159.487,44.958 185.623,45.822 88.163,47.244 81.255,47.523 124.536,49.098 131.496,52.629 87.3,53.492 82.982,54.051 149.962,62.027 185.496,62.992 208,64 37.5,65 108.153,66.116 112.852,66.65 128,67 104.572,67.437 116.2,68.6 144,72 152,72 160,72 168,72 208,72 116.383,73.457 189.41,73.753 112.547,74.676 117.754,78.842 64,80 72,80 144,80 168,80 176,80 184,80 192,80 208,80 103.353,80.543 119.736,81.001 96.774,83.464 64,88 72,88 80,88 208,88 98.552,90.119 110.185,91.923 182.601,94.818 208,96 137.109,97.358 132.5,97.5 134.798,102.387 50,102.5 149.454,102.591 121.056,102.997 107.544,103.353 168.605,103.556 208,104 102.26,106.07 187.5,110 195,110 202.5,110 35.281,110.973 96,112 208,112 125,112.5 130,112.5 135,112.5 62.154,115.443 96,120 208,120 144,128 152,128 160,128 168,128 176,128 184,128 192,128 200,128
GND_IO: J2.6 U9.2 U9.4 U9.6 U9.8 U10.2 | length 49.6
  Top Layer w0.254: U9.8 69.063,103.898 69.063,102.21 69.52,101.752 71.73,101.752 ; U9.6 71.755,101.778 71.73,101.752 ; U9.4 74.295,101.752 ; U9.2 76.835,101.803 76.886,101.752 ; U10.2 83.236,101.803 83.185,101.752 ; J2.6 87.96,104.803 86.489,103.332 86.489,102.135 86.106,101.752 83.185,101.752 ; 71.73,101.752 74.295,101.752 ; 74.295,101.752 76.886,101.752 ; 76.886,101.752 83.185,101.752
GREEN: R11.1 U2.61 U15.3 | length 68.5
  Top Layer w0.203: U2.61 120.908,64.893 121.844,63.957 158.267,63.957 162.763,59.461 168.554,59.461 168.885,59.131 U15.3 168.885,51.576 R11.1
MOTO_START: R23.1 R33.2 U2.29 | length 71.1
  Top Layer w0.254: R23.1 99.39,56.083 108.712,46.761 R33.2 ; v1(98.196,62.179) 98.374,62.179 98.476,62.281 98.476,62.56 98.831,62.916 98.831,63.983 99.593,64.745 99.593,83.947 101.625,85.979 108.991,85.979 109.728,86.716 109.728,88.113 112.243,90.627 115.164,90.627 116.408,89.382 U2.29
  Bottom Layer w0.254: v1(98.196,62.179) 98.196,60.681 98.73,60.147 98.73,56.464 98.527,56.261 v1(98.476,56.312)
NetBT1_1: BT1.1 R12.2 U2.1 | length 62.7
  Top Layer w0.254: BT1.1 90.728,78.69 94.615,74.803 ; R12.2 94.615,74.803 ; v2(98.247,73.66) 97.104,74.803 94.615,74.803 ; v2(103.327,73.66) 109.601,73.66 v2(109.652,73.711) ; U2.1 125.87,77.203 126.822,76.251 126.822,73.482 v2(126.924,73.381)
  Bottom Layer w0.254: v2(98.247,73.66) v2(103.327,73.66) ; v2(109.652,73.711) 111.227,72.136 125.679,72.136 v2(126.924,73.381)
NetC5_1: C5.1 C6.1 J3.1 L2.1 | length 14.2
  Top Layer w0.5: L2.1@102.808,112 C6.1 108.3,112.2 C5.1 108.5,116.5 J3.1@108.5,120.7
NetC7_2: C7.2 U2.6 Y1.2 | length 16.7
  Top Layer w0.254: U2.6@124.231,79.703 131.596,79.703 132.85,80.958 Y1.2 C7.2@138.046,83.366
NetC8_2: C8.2 U2.5 Y1.1 | length 14
  Top Layer w0.254: U2.5 130.016,79.203 130.933,78.286 Y1.1 ; Y1.1@133.068,78.069 C8.2
NetC9_2: C9.2 S2.2 U2.7 | length 36
  Top Layer w0.254: U2.7 128.26,80.203 129.972,81.915 129.972,85.039 130.124,85.192 130.124,85.293 130.886,86.055 145.618,86.055 147.625,84.049 C9.2 150.89,79.948 S2.2
NetC16_2: C16.2 Q1.1 R22.2 R24.1 U7.4 | length 26.6
  Top Layer w0.254: R24.1 195.275,70.296 197.22,70.296 197.471,70.547 C16.2 202.373,70.547 202.565,70.739 ; R22.2 202.108,64.414 202.108,66.954 202.565,67.412 202.565,70.739 ; U7.4 202.565,70.739
  Top Layer w0.5: Q1.1 R24.1
NetD1_2: D1.2 L1.1 U1.2 | length 15.4
  Top Layer w0.5: L1.1@49.985,65.405 50.06,65.479 U1.2
NetD2_2: D2.2 R1.2 | length 4.1
  Top Layer w0.203: D2.2 63.017,33.477 R1.2
NetD3_2: D3.2 R2.2 | length 4.1
  Top Layer w0.203: D3.2 69.858,33.418 R2.2
NetD4_2: D4.2 R3.2 | length 4.1
  Top Layer w0.203: R3.2 76.7,33.393 D4.2
NetD5_2: D5.2 R4.2 | length 4.1
  Top Layer w0.203: R4.2 83.541,33.452 D5.2
NetD8_1: D8.1 R20.1 | length 10.6
  Top Layer w0.254: D8.1 46.685,32.918 R20.1
NetD9_1: D9.1 J9.2 Q1.2 | length 19.6
  Top Layer w0.5: J9.2 190.023,46.183 D9.1 189.85,53.179 Q1.2
NetJ2_1: J2.1 R15.1 | length 6.6
  Top Layer w0.5: 70.5,114.3 J2.1@70.5,120.9
NetJ2_2: J2.2 R16.1 | length 6.6
  Top Layer w0.5: 74,114.3 J2.2@74,120.9
NetJ2_3: J2.3 R17.1 | length 6.6
  Top Layer w0.5: 77.5,114.3 J2.3@77.5,120.9
NetJ2_4: J2.4 R18.1 | length 6.6
  Top Layer w0.5: 81,114.3 J2.4@81,120.9
NetJ2_5: J2.5 R19.1 | length 6.6
  Top Layer w0.5: 84.5,114.3 J2.5@84.5,120.9
NetJ6_2: J6.2 U15.2 | length 20.8
  Top Layer w0.254: U15.2 166.345,42.723 167.538,41.529 169.545,41.529 170.51,40.564 170.51,37.597 J6.2
NetJ6_3: J6.3 U15.4 | length 19.6
  Top Layer w0.254: v1(168.681,42.951) 171.425,45.695 U15.4 U15.4@171.399,55.245
  Bottom Layer w0.254: J6.3 167.168,41.438 v1(168.681,42.951)
NetJ6_4: J6.4 U15.6 | length 34.9
  Top Layer w0.254: J6.4 166.817,34.29 176.047,34.29 176.505,34.747 U15.6
NetJ7_1: J7.1 U8.8 | length 13.9
  Top Layer w0.254: U8.8 148.158,37.49 J7.1
NetJ7_2: J7.2 U8.6 | length 14.3
  Top Layer w0.254: J7.2 144.678,37.47 144.678,41.199 145.618,42.139 U8.6
NetJ7_3: J7.3 U8.4 | length 14.7
  Top Layer w0.254: J7.3 141.234,40.6 143.078,42.443 U8.4
NetJ7_4: J7.4 U8.2 | length 15.1
  Top Layer w0.254: J7.4 137.734,39.64 140.538,42.443 U8.2
NetJ10_3: J10.3 R33.1 | length 5.3
  Top Layer w0.254: R33.1 108.712,37.425 J10.3
NetJ10_4: J10.4 R34.1 | length 5.3
  Top Layer w0.254: J10.4 105.224,37.416 R34.1
NetJ10_5: J10.5 R35.1 | length 5.3
  Top Layer w0.254: J10.5 101.735,37.427 R35.1
NetJ10_6: J10.6 R36.1 | length 5.3
  Top Layer w0.254: J10.6 98.247,37.439 R36.1
NetR15_2: R15.2 U9.7 | length 6
  Top Layer w0.254: R15.2 70.566,110.794 U9.7@70.566,104.884
NetR16_2: R16.2 U9.5 | length 7.2
  Top Layer w0.254: U9.5 73.025,107.381 74,108.356 R16.2
NetR17_2: R17.2 U9.3 | length 9.3
  Top Layer w0.254: U9.3 75.565,106.324 77.5,108.259 R17.2 77.5,109.139
NetR18_2: R18.2 U9.1 | length 8
  Top Layer w0.254: U9.1 78.105,106.629 81,109.524 R18.2
NetR19_2: R19.2 U10.1 | length 6.6
  Top Layer w0.254: U10.1@84.5,104.279 R19.2
NetR21_2: R21.2 U7.2 | length 4.8
  Top Layer w0.254: U7.2 201.168,88.798 R21.2
NetR29_1: R29.1 U8.7 | length 24.4
  Top Layer w0.254: R29.1 137.236,42.062 v1(137.465,41.834) ; U8.7 146.888,41.148 146.66,40.919 146.914,40.919 v1(147.041,41.046)
  Bottom Layer w0.254: v1(137.465,41.834) 137.566,41.834 138.354,41.046 v1(147.041,41.046)
NetR30_1: R30.1 U8.5 | length 18.4
  Top Layer w0.254: R30.1 138.735,44.221 v1(139.04,43.917) ; U8.5 144.348,43.967 v1(144.45,43.866)
  Bottom Layer w0.254: v1(139.04,43.917) 138.963,43.993 144.323,43.993 v1(144.45,43.866)
NetR43_1: R43.1 U8.3 | length 12.7
  Top Layer w0.254: R43.1 v1(139.04,46.38) ; v1(141.707,46.38) 141.808,46.482 U8.3
  Bottom Layer w0.254: v1(139.04,46.38) v1(141.707,46.38)
NetR44_1: R44.1 U8.1 | length 8.1
  Top Layer w0.254: R44.1@134.188,48.311 R44.1 138.557,48.539 139.268,49.251 ; 139.268,49.174 139.268,49.251 ; U8.1 139.268,49.251
NetU4_1: U4.1 U5.4 | length 39.5
  Top Layer w0.254: U5.4 139.714,106.948 140.575,106.948 141.275,106.248 141.275,96.317 142.138,95.453 164.744,95.453 165.684,96.393 U4.1
NetU4_3: U4.3 U6.4 | length 20.7
  Top Layer w0.254: U6.4 156.556,105.42 160.401,101.575 160.401,97.765 U4.3
PA0: U2.14 U3.4 | length 30.9
  Top Layer w0.254: U3.4 119.55,106.063 119.939,106.451 124.384,106.451 126.111,104.724 v2@126.111,102.26 ; U2.14 125.537,83.703 126.289,84.455 126.289,98.527 v2(126.314,98.552)
  Bottom Layer w0.254: v2@126.111,102.26 126.111,99.593 126.111,98.755 v2(126.314,98.552)
  other v2: 126.187,102.819
PA1: R39.1 U2.15 U9.10 | length 73.4
  Top Layer w0.254: R39.1 70.383,99.048 U9.10 ; v1(82.017,94.793) 86.766,94.793 87.271,95.298 123.6,95.298 124.104,94.793 124.104,86.182 122.758,84.836 122.758,84.226 122.781,84.203 U2.15
  Bottom Layer w0.254: v1(70.409,95.098) 70.434,95.098 71.526,94.005 81.458,94.005 82.017,94.564 v1(82.017,94.793)
PA2: R40.1 U2.16 U9.12 | length 70.2
  Top Layer w0.254: R40.1 72.983,99.108 U9.12 ; v1(79.096,94.894) 79.248,95.047 79.299,94.996 80.594,94.996 81.35,95.752 124.238,95.752 125.476,94.513 125.476,84.912 125.267,84.703 U2.16
  Bottom Layer w0.254: v1(73.076,95.275) 73.457,94.894 v1(79.096,94.894)
PA3: R41.1 U2.17 U9.14 | length 67.2
  Top Layer w0.254: U9.14 U9.14@75.582,99.133 ; R41.1 U9.14@75.582,99.133 ; v1(75.59,96.596) 75.59,99.125 U9.14@75.582,99.133 ; v1(79.756,96.596) 79.804,96.644 121.282,96.644 v2(122.098,97.46) v2@121.835,97.723 ; v2(122.377,94.107) 123.19,93.294 123.19,90.571 122.408,89.789 U2.17
  Bottom Layer w0.254: v1(75.59,96.596) v1(79.756,96.596) ; v2(122.098,97.46) 122.098,95.453 122.377,95.174 v2(122.377,94.107)
PA4: R42.1 U2.20 U9.16 | length 61.7
  Top Layer w0.254: R42.1 78.105,93.512 U9.16 79.59,99.15 81.356,97.384 86.614,97.384 87.452,98.222 119.659,98.222 v2(120.294,98.857) ; v2(120.447,94.336) 120.908,93.874 U2.20
  Bottom Layer w0.254: v2(120.447,94.336) v2@120.447,98.704
PA5: R45.1 U2.21 U10.4 | length 54.5
  Top Layer w0.254: R45.1 84.876,93.435 v1(85.09,93.65) 85.192,93.548 87.173,93.548 88.113,94.488 118.008,94.488 118.11,94.488 120.408,92.19 U2.21 ; U10.4 85.75,99.289 v1(86.106,98.933)
  Bottom Layer w0.254: v1(85.09,93.65) 85.09,97.485 86.106,98.501 v1(86.106,98.933)
PA6: U2.22
PA7: U2.23
PA8: U2.41
PA9: U2.42
PA10: U2.43
PA11: U2.44
PA12: U2.45
PA13: J8.2 U2.46 | length 25.3
  Top Layer w0.254: J8.2 110.465,58.166 111.811,59.512 114.249,61.951 114.249,76.581 114.757,77.089 114.757,77.724 114.278,78.203 U2.46
PA14: J8.3 U2.49 | length 20.1
  Top Layer w0.254: J8.3 113.005,60.064 114.908,61.968 U2.49
PA15: U2.50
PB3: R1.1 U2.55 | length 90
  Top Layer w0.203: R1.1 66.802,40.005 68.428,41.631 73.536,41.631 73.965,42.059 80.264,42.059 81.367,43.163 91.508,43.163 92.313,43.967 v1(96.342,43.967) ; v1(111.176,43.663) 114.656,43.663 115.519,42.799 117.424,42.799 117.908,43.283 117.908,63.348 U2.55
  Bottom Layer w0.203: v1(96.342,43.967) 97.46,42.85 109.957,42.85 110.769,43.663 v1(111.176,43.663)
PB4: R2.1 U2.56 | length 83.9
  Top Layer w0.254: R2.1 72.517,40.005 74.143,41.631 81.229,41.631 81.915,42.316 85.319,42.316 85.649,42.647 92.126,42.647 v1(92.177,42.697) ; v1(113.462,42.799) 114.325,42.799 115.011,42.113 117.78,42.113 118.408,42.742 U2.56
  Bottom Layer w0.254: v1(92.177,42.697) 93.193,42.697 93.777,43.282 95.733,43.282 96.647,42.367 110.16,42.367 110.541,42.748 112.954,42.748 113.208,42.494 113.462,42.748 v1(113.462,42.799)
PB5: R3.1 U2.57 | length 76.9
  Top Layer w0.254: R3.1 81.153,40.005 82.677,41.529 85.623,41.529 85.928,41.834 v1(93.777,41.834) ; v1(111.862,41.732) 114.376,41.732 114.579,41.529 118.161,41.529 118.908,42.277 118.908,62.636 U2.57
  Bottom Layer w0.254: v1(93.777,41.834) 93.828,41.783 94.463,41.783 94.945,42.266 95.91,42.266 96.444,41.732 v1(111.862,41.732)
PB6: R4.1 U2.58 | length 70.9
  Top Layer w0.254: R4.1 85.852,40.005 86.843,40.996 v1(95.58,40.996) ; v1(113.157,40.818) 113.309,40.665 113.411,40.767 118.923,40.767 119.408,41.253 119.408,62.357 U2.58
  Bottom Layer w0.254: v1(95.58,40.996) 95.529,40.996 95.707,40.818 v1(113.157,40.818)
PB11: R26.1 R34.2 U2.30 | length 67.6
  Top Layer w0.254: R26.1 98.544,54.161 105.224,47.481 R34.2 ; v1(99.644,61.976) 99.492,62.128 99.492,63.449 100.228,64.186 100.228,83.464 102.057,85.293 109.576,85.293 110.541,86.258 110.541,87.859 112.674,89.992 114.757,89.992 115.908,88.841 U2.30
  Bottom Layer w0.254: v1(98.476,54.178) 100.457,56.159 100.457,59.461 99.644,60.274 v1(99.644,61.976)
PB12: R31.1 R35.2 U2.33 | length 57.2
  Top Layer w0.254: R31.1 98.662,52.239 101.575,49.327 101.575,45.398 R35.2 ; v1(100.559,62.865) 100.533,62.865 100.863,63.195 100.863,83.21 102.356,84.703 U2.33
  Bottom Layer w0.254: v1(98.628,52.349) 98.679,52.299 99.847,52.299 100.914,53.365 100.914,60.909 100.559,61.265 v1(100.559,62.865)
PB13: R32.1 R36.2 U2.34 | length 55.2
  Top Layer w0.254: R32.1 97.079,50.317 98.247,49.149 R36.2 ; v1(101.524,61.798) 101.524,82.933 102.794,84.203 U2.34
  Bottom Layer w0.254: v1(98.146,49.327) 98.247,49.428 99.974,49.428 101.524,50.978 v1(101.524,61.798)
PC0: R9.2 S1.1 U2.8 | length 74.6
  Top Layer w0.254: U2.8 127.16,80.703 129.311,82.855 129.311,85.649 130.327,86.665 180.391,86.665 181.458,87.732 188.3,87.732 188.397,87.635 188.397,93.375 S1.1
PC1: R8.2 S1.2 U2.9 | length 84.8
  Top Layer w0.254: U2.9 127,81.203 128.857,83.061 128.857,85.837 130.139,87.119 179.575,87.119 180.823,88.367 184.658,88.367 186.08,89.789 186.08,94.285 187.706,95.91 190.068,95.91 190.877,95.102 S1.2 R8.2@190.877,87.671
PC2: R6.2 S1.3 U2.10 | length 86.7
  Top Layer w0.254: U2.10 126.858,81.703 128.403,83.249 128.403,86.025 129.951,87.573 179.038,87.573 180.34,88.875 184.226,88.875 185.445,90.094 185.471,90.094 185.471,94.666 187.274,96.469 190.382,96.469 S1.3 R6.2@193.417,87.648
PC3: R5.2 S1.4 U2.11 | length 89.2
  Top Layer w0.254: U2.11 126.603,82.203 127.949,83.55 127.949,86.213 129.763,88.027 178.629,88.027 180.111,89.51 183.972,89.51 185.014,90.551 185.014,94.92 187.017,96.923 192.468,96.923 S1.4 195.957,87.645 R5.2@195.947,87.635
PC4: R28.1 U2.24 U8.10 | length 83.2
  Top Layer w0.203: v1(115.392,79.807) 116.459,79.807 117.704,81.051 117.704,83.947 118.908,85.152 U2.24 ; v1(125.781,62.332) 125.959,62.332 126.644,63.017 145.39,63.017 146.888,61.519 146.888,60.198 ; U8.10 146.888,60.198 ; R28.1 153.159,59.896 152.806,60.249 146.939,60.249 146.888,60.198
  Bottom Layer w0.203: v1(115.392,79.807) 114.224,79.807 113.462,80.569 109.423,80.569 108.509,79.654 108.509,72.692 109.652,71.549 121.615,71.549 122.961,70.202 122.961,65.151 v1(125.781,62.332)
PC5: R27.1 U2.25 U8.12 | length 84.5
  Top Layer w0.203: v1(115.545,81.051) 116.589,81.051 117.3,81.763 117.3,84.28 118.408,85.388 U2.25 ; v1(123.419,62.433) 124.322,61.53 126.757,61.53 127.635,62.408 143.256,62.408 144.348,61.316 U8.12 144.348,55.061 145.085,54.324 150.108,54.324 152.239,56.456 R27.1
  Bottom Layer w0.203: v1(115.545,81.051) 109.245,81.051 107.925,79.731 107.925,72.593 109.372,71.145 121.285,71.145 122.298,70.133 122.298,64.113 123.419,62.992 v1(123.419,62.433)
PC6: R38.1 U2.37 U8.14 | length 80.4
  Top Layer w0.203: v1(108.941,83.058) 109.245,83.058 109.626,83.439 111.125,83.439 111.861,82.703 U2.37 ; v1(120.472,63.017) 121.539,63.017 123.596,60.96 127.203,60.96 128.168,61.925 140.97,61.925 141.808,61.087 U8.14 141.808,54.889 142.777,53.921 151.101,53.921 151.799,54.618 R38.1
  Bottom Layer w0.203: v1(108.941,83.058) 108.941,82.864 106.959,80.883 106.959,71.755 106.934,71.73 108.509,70.155 120.65,70.155 121.488,69.317 121.488,63.856 120.574,62.941 120.498,63.017 v1(120.472,63.017)
PC7: R37.1 U2.38 U8.16 | length 80.2
  Top Layer w0.203: v1(110.642,82.194) 110.651,82.203 U2.38 ; v1(121.412,61.646) 122.896,60.161 127.878,60.161 129.184,61.468 138.303,61.468 139.268,60.503 U8.16 139.268,54 139.751,53.518 150.724,53.518 151.511,52.73 153.108,52.73 R37.1
  Bottom Layer w0.203: v1(110.642,82.194) 108.941,82.194 107.521,80.775 107.521,72.133 108.991,70.663 120.625,70.663 120.729,70.558 120.817,70.558 121.891,69.484 121.891,63.96 ; v1(121.412,61.646) 121.891,62.125 121.891,63.96 ; 121.895,62.408 121.895,63.957 121.891,63.96
PC8: U2.39
PC9: U2.40
PC10: U2.51
PC11: U2.52
PC12: U2.53
PC13: U2.2
PC14: C10.2 U2.3 Y2.2 | length 19.5
  Top Layer w0.254: U2.3 127.765,78.203 129.362,76.606 129.362,69.774 130.578,68.558 Y2.2 C10.2@133.079,65.941
PC15: C11.2 U2.4 Y2.1 | length 16.9
  Top Layer w0.254: U2.4 128.459,78.703 129.845,77.318 129.845,72.568 130.937,71.476 132.897,71.476 Y2.1 133.079,73.683 C11.2
PD2: U2.54
RED: R10.1 U2.59 U15.1 | length 63.9
  Top Layer w0.203: U2.59 119.908,64.897 121.251,63.554 157.782,63.554 162.331,59.004 163.093,59.004 163.805,58.293 U15.1 163.805,51.576 R10.1
REJECT: R21.1 U2.28 | length 111.3
  Top Layer w0.254: v1(116.307,92.634) 116.18,92.634 115.57,92.024 115.57,91.262 116.908,89.924 U2.28 ; v1(128.854,91.338) 129.692,91.338 133.147,94.793 175.565,94.793 177.648,96.876 v1(177.648,103.175) ; v1(180.289,103.175) 198.45,103.175 201.219,100.406 R21.1
  Bottom Layer w0.254: v1(116.307,92.634) 116.332,92.659 119.278,92.659 120.599,91.338 v1(128.854,91.338) ; v1(177.648,103.175) v1(180.289,103.175)
TRIG1: U2.26 U5.1 U5.2 | length 39
  Top Layer w0.254: U2.26 117.908,88.343 118.44,88.875 119.355,88.875 v2(119.405,88.925) ; v2(127.432,88.798) 127.432,93.802 128.372,94.742 128.372,98.73 128.676,99.035 137.236,99.035 138.481,100.279 138.43,100.33 138.43,102.641 ; U5.2 139.064,102.792 138.913,102.641 138.43,102.641 ; 138.43,102.641 138.43,102.692 ; 138.43,102.692 138.43,103.753 U5.1 138.414,102.709 138.43,102.692
  Bottom Layer w0.254: v2(119.405,88.925) 127.305,88.925 v2(127.432,88.798)
TRIG1+: J4.2 R13.1 | length 4.9
  Top Layer w0.254: J4.2 144.23,112.945 R13.1
TRIG1-: J4.3 U4.2 | length 35.9
  Top Layer w0.254: J4.3 147,113.045 148.717,111.328 161.747,111.328 v1(161.925,111.506) ; U4.2 U4.2@163.294,97.711
  Bottom Layer w0.254: v1(161.925,111.506) 161.925,110.848 160.909,109.832 160.909,99.797 U4.2
TRIG2: U2.27 U6.1 U6.2 | length 45.2
  Top Layer w0.254: U2.27 117.408,90.535 v2(117.653,90.78) ; v1(129.819,90.297) 130.302,90.297 133.985,93.98 143.231,93.98 143.815,93.396 v1(144.272,93.396) ; v1(144.094,97.663) 144.12,97.688 144.12,102.413 ; U6.1 144.12,103.664 144.12,102.413 ; U6.2 144.764,102.574 144.551,102.362 144.17,102.362 144.12,102.413
  Bottom Layer w0.254: v2(117.653,90.78) 119.405,90.78 119.888,90.297 v1(129.819,90.297) ; v1(144.094,97.663) 144.272,97.485 v1(144.272,93.396)
TRIG2+: J5.2 R14.1 | length 4.9
  Top Layer w0.254: J5.2 178.93,112.662 R14.1
TRIG2-: J5.3 U4.4 | length 39.8
  Bottom Layer w0.254: U4.4 160.3,99.797 160.3,113.386 162.001,115.087 179.307,115.087 J5.3
TRIG_INPUT: J3.3 R7.1 U3.2 | length 22.6
  Top Layer w0.254: U3.2 118.9,106.581 120.98,108.661 120.98,111.76 120.54,112.2 R7.1
  Top Layer w0.5: J3.3@115.5,120.7 115.5,116.021 115.875,115.646 118.542,115.646 119.2,114.988 R7.1
YELLOW: R25.1 U2.62 U15.5 | length 72.6
  Top Layer w0.203: U2.62 121.408,65.459 122.403,64.465 158.394,64.465 162.56,60.3 172.644,60.3 173.965,58.979 U15.5 173.965,51.627 R25.1
pads on no net: BT1.0 J1.0 J4.4 J4.5 J4.7 J4.8 J4.9 J5.4 J5.5 J5.7 J5.8 J5.9 S2.1 S2.3 S2.4 U2.35 U2.36 U3.1 U4.5 U4.6 U4.8 U4.9 U4.10 U4.11 U4.12 U4.13 U15.8 U15.9 U15.10 U15.11 U15.12 U15.13

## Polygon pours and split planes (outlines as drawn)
GND on Top Layer "Top Layer-No Net" (solid, remove dead copper, pour order 2): 30,129.9 30.1,130 210,130 210,30 30,30
GND on Bottom Layer "Top Layer-No Net" (solid, remove dead copper, pour order 4): 30.1,130 210,130 210,30 30.2,30 30.1,30.1

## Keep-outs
Keep-Out Layer:
  lines w0.1: 30,129.9 30.1,130 ; 30.1,130 210,130 210,30 30,30 30.1,30.1 30.1,130

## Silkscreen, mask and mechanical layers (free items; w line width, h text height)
Top Overlay:
  text "HOST-IO" at 62.662,120.447 h1 r90
  text "POWER" at 45.923,120.193 h1 r90
  text "FIBER" at 100.559,119.812 h1 r90
  text "CAMERA1" at 130.505,118.669 h1 r90
  text "CAMERA2" at 165.608,118.542 h1 r90
  text "1" at 69.748,118.008 h0.8
  text "1" at 106.502,118.008 h0.8
  text "4" at 118.974,117.856 h0.8
  text "6" at 87.63,117.729 h0.8
  text "FD2000" at 167.386,76.733 h1.5
  text "2014 12.22" at 167.259,73.965 h1.5
  text "4" at 116.002,57.455 h0.8
  text "1" at 105.766,55.778 h0.8
  text "LAMP" at 157.683,42.291 h1 r90
  text "BOTTON" at 125.476,42.164 h1 r90
  text "REJECT" at 184.861,42.164 h1 r90
  text "2" at 188.341,40.589 h0.8
  text "1" at 194.767,40.589 h0.8
  text "6" at 97.587,40.005 h1
  text "4" at 163.068,40.005 h1
  text "1" at 174.142,40.005 h1
  text "1" at 115.722,39.878 h1
  text "6" at 129.718,39.878 h1
  text "1" at 148.539,39.726 h1
  text "RELAY" at 90.348,36.881 h1 r90
  text "POWER" at 64.948,0 h1 r90
Mechanical 1:
  the board outline again, w0.1

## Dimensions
213,130 to 217,30 on Mechanical 13
30,24 to 210,24 on Mechanical 13
30,137 to 35,132 on Mechanical 13
210,137 to 182,136 on Mechanical 13
182,139 to 147,137 on Mechanical 13
147,136.746 to 114,135 on Mechanical 13
114,138 to 79,136 on Mechanical 13
79,137 to 52,138 on Mechanical 13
